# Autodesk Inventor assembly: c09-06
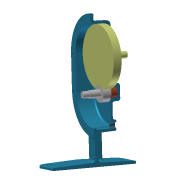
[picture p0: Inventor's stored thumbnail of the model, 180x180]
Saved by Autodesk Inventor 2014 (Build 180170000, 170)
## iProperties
Created: 2010-12
Part Number: c09-06
Document SubType Name: Assembly
Designer: Thom Tremblay
Author: Thom Tremblay
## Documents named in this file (5)
- C:\Inventor 2014 Essentials\Assemblies\Chapter 09\c09-06.iam
- C:\Inventor 2014 Essentials\Content Center Files\en-US\ISO 2795  F\ISO 2795 - 10 x 14 x 10F.ipt
- C:\Inventor 2014 Essentials\Parts\Chapter 09\c09-11.ipt
- C:\Inventor 2014 Essentials\Assemblies\Chapter 09\Design Accelerators\Blank Input Shaft 2.iam
- C:\Inventor 2014 Essentials\Assemblies\Chapter 09\Design Accelerators\Blank Transfer Shaft.iam
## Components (5 placed, 4 different names)
1. c09-11:1 — Insert:27, Insert:28
2. ISO 2795 (Flanged) 10 x 14 x 10:2 — Insert:27, Insert:30
3. ISO 2795 (Flanged) 10 x 14 x 10:3 — Insert:28, Insert:29
4. Blank Input Shaft 2:1 [sub-assembly] — Insert:29
5. Blank Transfer Shaft:1 [sub-assembly] — Insert:30
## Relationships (4: Insert 4)
- Insert:27: c09-11:1 ↔ ISO 2795 (Flanged) 10 x 14 x 10:2
- Insert:28: c09-11:1 ↔ ISO 2795 (Flanged) 10 x 14 x 10:3
- Insert:29: ISO 2795 (Flanged) 10 x 14 x 10:3 ↔ Blank Input Shaft 2:1
- Insert:30: ISO 2795 (Flanged) 10 x 14 x 10:2 ↔ Blank Transfer Shaft:1
